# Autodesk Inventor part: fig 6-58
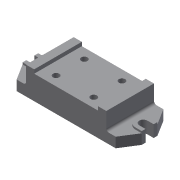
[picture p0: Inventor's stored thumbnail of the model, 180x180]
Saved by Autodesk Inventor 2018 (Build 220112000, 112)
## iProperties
Shininess: 77.0
Angle Display Precision: 2
Document Length Units: 11269
Document Angle Units: 11279
Document Time Units: 11290
Document Mass Units: 11283
Document Length Units Precision: 3
Document Angle Units Precision: 2
Created: 2001-12
Part Number: fig 6-58
Document SubType Name: Modeling
Designer: Renu Muthoo
Density: 1 g/cm^3
Material: Generic
Appearance: Default
Density: 0.0
Volumn: 0.0
Area: 0.0
PropertySet Name: Model Information
Control State: 0
Master: False
Checked Out: False
Author: Renu Muthoo
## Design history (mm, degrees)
sketch "Sketch3"
  geometry: L1 (-59.119, -24.322)-(-59.119, 19.678); L2 (-59.119, 19.678)-(-46.119, 19.678); L3 (-46.119, 19.678)-(-46.119, 13.678); L4 (-46.119, 13.678)-(55.881, 13.678); L5 (55.881, 13.678)-(55.881, 19.678); L6 (55.881, 19.678)-(68.881, 19.678); L7 (68.881, 19.678)-(68.881, -24.322); L8 (68.881, -24.322)-(-59.119, -24.322)
  constraints: 16 end point, 2 equal length
  dimensions: "d10" = 13 distance of L1.end L2.end; "d11" = 102 distance of L3.end L4.end; "d13" = 44 distance between parallel lines of L2 L8; "d14" = 6 distance of L2.end L3.end
extrude "Extrusion1" new body sketch "Sketch3" distance "d15" = 76; taper "d16" = 0 deg
sketch "Sketch4"
  geometry: L1 (0, 0)-(0, 76) reference; L2 (0, 76)-(-15, 76); L3 (-15, 76)-(-31, 50.5); L4 (-31, 50.5)-(-31, 44.5); L5 (-31, 44.5)-(-21, 44.5); L6 (-21, 31.5)-(-31, 31.5); L7 (-31, 31.5)-(-31, 25.5); L8 (-31, 25.5)-(-15, 0); L9 (-15, 0)-(0, 0); L10 (128, 76)-(0, 76) reference; L11 (0, 0)-(128, 0) reference; A1 r 6.5 centre (-21, 38) between (-21, 31.5) and (-21, 44.5)
  constraints: 16 end point, 4 equal length, 3 collinear, 3 parallel, 2 perpendicular, 2 point on circle, 2 tangent, 1 centre point
  dimensions: "d17" = 13 distance between parallel lines of L6 L5; "d18" = 25 distance of L3.end L7.end; "d19" = 10 distance of L6.start L6.end; "d20" = 15 distance of L8.end L1.start; "d21" = 16 horizontal distance of L7.end L8.end
extrude "Extrusion2" join sketch "Sketch4" distance "d22" = 16; taper "d23" = 0 deg
sketch "Sketch5"
  geometry: L1 (-159, 44.5)-(-159, 50.5) reference; L2 (-149, 44.5)-(-159, 44.5) reference; L3 (-159, 31.5)-(-149, 31.5) reference; L4 (-159, 25.5)-(-159, 31.5) reference; L5 (-159, 25.5)-(-149, 25.5); L6 (-149, 50.5)-(-159, 50.5); A1 r 6.5 centre (-149, 38) between (-149, 31.5) and (-149, 44.5) reference; A2 r 12.5 centre (-149, 38) between (-149, 25.5) and (-149, 50.5)
  constraints: 4 end point, 2 point on circle, 2 tangent, 1 centre point, 1 parallel, 1 perpendicular
extrude "Extrusion3" join sketch "Sketch5" distance "d24" = 19; taper "d25" = 0 deg
workplane "Work Plane1"
mirror "Mirror1"
fillet "Fillet1" dims "d27" = 4
sketch "Sketch6"
  geometry: L1 (0, 0)-(0, 76) reference; L2 (0, 0)-(102, 0) reference; 1 further point
  dimensions: "d28" = 20 distance from line of L1 point (20, 15); "d29" = 15 distance from line of L2 point (20, 15)
hole "Hole1" sketch "Sketch6" at (20, 15) diameter "d30" = 10; stored, may be unused: countersink angle "d34" = 82 deg, drill point angle "d36" = 118 deg; dims "d31" = 6, "d32" = 4, "d33" = 2, "d35" = 15
sketch "Sketch7"
  geometry: C1 r 5 at (20, 15) reference; 3 further points
  constraints: 4 other
pattern_linear "Rectangular Pattern2" dims "d45" = 45, "d48" = 60
body "Solid1"
other parameters: "d26" = -64
